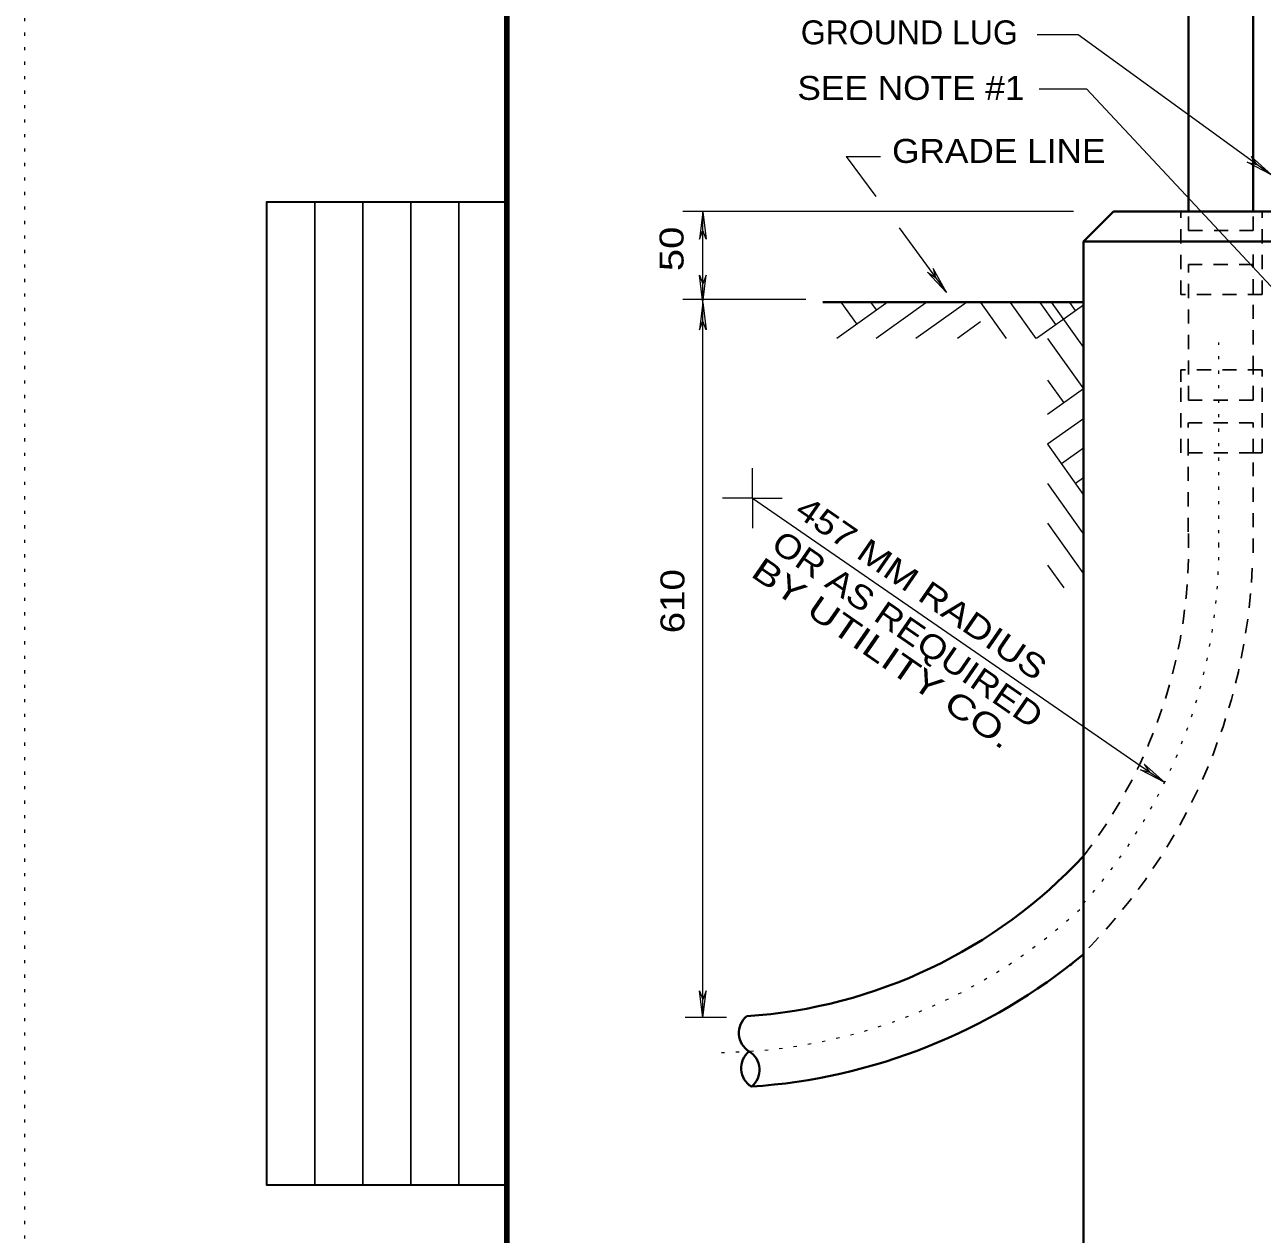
# Model space of a CAD drawing. Extents: x 312583 to 312854, y 144419 to 144597.
# Drawn here: x 312601.2 to 312640.47, y 144489.1 to 144527.49 of the extents above; entities that cross this region are included whole.
import ezdxf

# ---------------------------------------------------------------- set-up
doc = ezdxf.new("R2010")
doc.units = 0
doc.header["$LTSCALE"] = 0.3
doc.linetypes.add('DOTTED', pattern=[1.5, 0.3, -1.2])
doc.linetypes.add('SHORT_DASHED', pattern=[2.7, 1.5, -1.2])
for name, color, linetype, lineweight in [('1', 7, 'Continuous', 25), ('2', 7, 'Continuous', 13), ('63', 7, 'DOTTED', 13)]:
    doc.layers.add(name, color=color, linetype=linetype, lineweight=lineweight)

msp = doc.modelspace()

# ---------------------------------------------------------------- linework, layer by layer
at = {"layer": '1', "lineweight": 40}
for p, q in [((312638.1265, 144521.597), (312638.1265, 144530.383)), ((312640.1811, 144521.5817), (312640.1811, 144530.383)), ((312634.7915, 144520.608), (312635.7498, 144521.5664)), ((312635.7498, 144521.5664), (312674.0831, 144521.5664)), ((312634.7915, 144520.608), (312634.7915, 144487.0664)), ((312634.7915, 144520.608), (312666.3475, 144520.608)), ((312634.7915, 144518.6914), (312626.5268, 144518.6914))]:
    msp.add_line(p, q, dxfattribs=at)
at = {"layer": '1'}
for p, q in [((312610.4087, 144490.6573), (312610.4087, 144521.8756)), ((312611.9315, 144490.6573), (312611.9315, 144521.8756)), ((312613.4543, 144490.6573), (312613.4543, 144521.8756)), ((312614.9772, 144490.6573), (312614.9772, 144521.8756))]:
    msp.add_line(p, q, dxfattribs=at)
at = {"layer": '1', "linetype": 'SHORT_DASHED'}
for p, q in [((312637.8811, 144518.929), (312637.8811, 144521.5664)), ((312638.1265, 144520.9607), (312638.1265, 144521.597)), ((312640.1811, 144520.9607), (312640.1811, 144521.6814)), ((312640.4648, 144518.929), (312640.4648, 144521.528)), ((312638.1265, 144520.9607), (312640.1811, 144520.9607)), ((312640.1811, 144516.537), (312640.1811, 144520.2017)), ((312640.1811, 144519.8874), (312638.1265, 144519.8874)), ((312638.1265, 144515.5787), (312638.1265, 144519.8874)), ((312640.4648, 144518.929), (312637.8811, 144518.929)), ((312640.4648, 144516.537), (312637.8811, 144516.537)), ((312640.1811, 144515.5787), (312640.1811, 144516.537)), ((312640.4648, 144513.8997), (312640.4648, 144516.537)), ((312640.1811, 144515.5787), (312638.1265, 144515.5787)), ((312640.1811, 144514.858), (312638.1265, 144514.858)), ((312640.1811, 144513.8997), (312640.1811, 144514.858)), ((312640.1811, 144510.7334), (312640.1811, 144513.593))]:
    msp.add_line(p, q, dxfattribs=at)
at = {"layer": '1', "linetype": 'DOTTED', "lineweight": 13}
msp.add_line((312639.0925, 144510.8944), (312639.0925, 144517.411), dxfattribs=at)
at = {"layer": '1', "lineweight": 158}
msp.add_lwpolyline([(312616.5, 144423.1446), (312616.5, 144585.0846), (312849, 144585.0846)], dxfattribs=at)
at = {"layer": '1', "lineweight": 35}
msp.add_lwpolyline([(312616.5, 144490.6573), (312608.8858, 144490.6573), (312608.8858, 144521.8756), (312616.5, 144521.8756)], dxfattribs=at)
at = {"layer": '1', "linetype": 'SHORT_DASHED'}
for points in [[(312640.4648, 144513.8997), (312640.1888, 144513.8997), (312637.8811, 144513.8997), (312637.8811, 144516.1537), (312637.8811, 144516.537)], [(312638.1188, 144511.3927), (312638.1188, 144513.8997), (312638.1188, 144514.858)]]:
    msp.add_lwpolyline(points, dxfattribs=at)
at = {"layer": '1', "linetype": 'DOTTED', "lineweight": 13}
for centre, radius, start, end in [((312622.1012, 144510.8924), 16.9913, 318.32481, 1.80031), ((312623.0528, 144512.0156), 17.1494, 270.85045, 313.38554)]:
    msp.add_arc(centre, radius, start, end, dxfattribs=at)
at = {"layer": '1', "linetype": 'SHORT_DASHED'}
for centre, radius, start, end in [((312622.1012, 144510.8924), 16.0281, 322.35486, 1.79879), ((312621.6968, 144511.0448), 18.4719, 313.3975, 358.54034)]:
    msp.add_arc(centre, radius, start, end, dxfattribs=at)
at = {"layer": '1', "lineweight": 40}
for centre, radius, start, end in [((312623.0528, 144512.0156), 16.0281, 273.78468, 317.09104), ((312623.0126, 144512.2149), 18.4719, 273.88001, 309.60271), ((312624.5466, 144495.4891), 0.6883, 129.27151, 238.27842), ((312624.6203, 144494.3707), 0.6883, 129.27151, 238.27842), ((312623.8267, 144494.3157), 0.6883, 309.6625, 58.66941)]:
    msp.add_arc(centre, radius, start, end, dxfattribs=at)
at = {"layer": '2'}
for p, q in [((312633.3224, 144527.186), (312634.6228, 144527.186)), ((312634.6228, 144527.186), (312640.7638, 144522.724)), ((312633.3925, 144525.4534), (312634.8911, 144525.4534)), ((312634.8911, 144525.4534), (312644.3595, 144515.318)), ((312627.2628, 144523.3144), (312628.3579, 144523.3144)), ((312627.2628, 144523.3144), (312628.2058, 144522.0417)), ((312640.1198, 144523.3067), (312640.2808, 144523.0614)), ((312640.7638, 144522.724), (312640.1198, 144523.3067)), ((312639.9895, 144523.1304), (312640.2808, 144523.0614)), ((312640.7638, 144522.724), (312639.9895, 144523.1304)), ((312634.4771, 144521.5664), (312622.0801, 144521.5664)), ((312622.7142, 144521.5489), (312622.6068, 144520.6825)), ((312622.7142, 144521.5489), (312622.8215, 144520.6825)), ((312622.6068, 144520.6825), (312622.7142, 144520.9585)), ((312622.8215, 144520.6825), (312622.7142, 144520.9585)), ((312628.9418, 144521.045), (312630.4521, 144518.998)), ((312630.0228, 144519.757), (312630.0995, 144519.4734)), ((312630.4521, 144518.998), (312630.0228, 144519.757)), ((312622.6068, 144519.5402), (312622.7142, 144519.2642)), ((312622.7142, 144518.6739), (312622.6068, 144519.5402)), ((312622.6068, 144519.5402), (312622.7142, 144519.2642)), ((312622.7142, 144518.6739), (312622.6068, 144519.5402)), ((312622.8215, 144519.5402), (312622.7142, 144519.2642)), ((312622.7142, 144518.6739), (312622.8215, 144519.5402)), ((312622.8215, 144519.5402), (312622.7142, 144519.2642)), ((312622.7142, 144518.6739), (312622.8215, 144519.5402)), ((312629.8465, 144519.6344), (312630.0995, 144519.4734)), ((312630.4521, 144518.998), (312629.8465, 144519.6344)), ((312625.9825, 144518.7757), (312622.0817, 144518.7757)), ((312622.7142, 144518.6739), (312622.6068, 144517.8075)), ((312622.7142, 144518.6739), (312622.8215, 144517.8075)), ((312626.9638, 144517.549), (312628.5968, 144518.7067)), ((312627.0941, 144518.6914), (312627.5925, 144517.9937)), ((312628.0371, 144518.6914), (312628.2135, 144518.4384)), ((312628.2135, 144517.549), (312629.7775, 144518.6607)), ((312629.4785, 144517.549), (312631.0808, 144518.6914)), ((312631.5255, 144518.676), (312632.3381, 144517.5337)), ((312632.4685, 144518.676), (312633.2811, 144517.5337)), ((312633.3041, 144517.549), (312634.7915, 144518.607)), ((312633.4115, 144518.676), (312633.9098, 144517.9784)), ((312633.7641, 144518.6914), (312634.7915, 144517.25)), ((312634.3545, 144518.676), (312634.5308, 144518.423)), ((312622.6068, 144517.8075), (312622.7142, 144518.0835)), ((312622.8215, 144517.8075), (312622.7142, 144518.0835)), ((312630.7971, 144517.549), (312631.5255, 144518.0704)), ((312633.6491, 144517.5337), (312634.7915, 144515.9314)), ((312633.6491, 144516.215), (312634.1705, 144515.4867)), ((312634.7915, 144515.9314), (312633.6491, 144515.1187)), ((312634.7915, 144514.9884), (312633.6491, 144514.1757)), ((312633.6491, 144514.1757), (312634.8068, 144512.5504)), ((312634.7915, 144514.053), (312634.0938, 144513.5547)), ((312624.2958, 144512.466), (312624.2958, 144513.4167)), ((312634.7915, 144513.11), (312634.5385, 144512.926)), ((312633.6491, 144512.9337), (312634.7608, 144511.3697)), ((312624.2958, 144512.466), (312623.3451, 144512.466)), ((312624.2958, 144512.466), (312637.3751, 144503.4424)), ((312624.2958, 144512.466), (312624.2958, 144511.5154)), ((312624.2958, 144512.466), (312625.2388, 144512.466)), ((312633.6491, 144511.6687), (312634.7915, 144510.0664)), ((312633.6491, 144510.3424), (312634.1705, 144509.6217)), ((312636.6008, 144503.841), (312636.8845, 144503.772)), ((312637.3751, 144503.4424), (312636.6008, 144503.841)), ((312636.7235, 144504.0174), (312636.8845, 144503.772)), ((312637.3751, 144503.4424), (312636.7235, 144504.0174)), ((312622.6068, 144496.8315), (312622.7142, 144496.5555)), ((312622.7142, 144495.9652), (312622.6068, 144496.8315)), ((312622.8215, 144496.8315), (312622.7142, 144496.5555)), ((312622.7142, 144495.9652), (312622.8215, 144496.8315)), ((312623.4678, 144495.9827), (312622.1508, 144495.9827))]:
    msp.add_line(p, q, dxfattribs=at)
msp.add_lwpolyline([(312622.7142, 144495.9652), (312622.7142, 144518.6739), (312622.7142, 144521.5489)], dxfattribs=at)
at = {"layer": '63'}
msp.add_line((312601.2, 144418.5846), (312601.2, 144596.7846), dxfattribs=at)

# ---------------------------------------------------------------- texts
at = {"layer": '2'}
msp.add_text('GROUND LUG', height=0.76, dxfattribs=at).set_placement((312625.8243, 144526.8708))
at = {"layer": '2', "width": 1.1}
for s, p in [('SEE NOTE #1', (312625.7167, 144525.1074)), ('GRADE LINE', (312628.7215, 144523.1075))]:
    msp.add_text(s, height=0.76, dxfattribs=at).set_placement(p)
at = {"layer": '2'}
for s, rotation, width, p in [('50 ', 90, 1.25, (312622.104, 144519.6711)), ('457 MM RADIUS', 325.385, 1.2, (312625.5894, 144511.9545)), ('OR AS REQUIRED', 325.385, 1.15, (312624.8312, 144510.867)), ('BY UTILITY CO.', 325.385, 1.3, (312624.1993, 144510.0071)), ('610 ', 90, 1.2, (312622.1325, 144508.1774))]:
    msp.add_text(s, height=0.76, rotation=rotation, dxfattribs=dict(at, width=width)).set_placement(p)

doc.saveas('drawing.dxf')
